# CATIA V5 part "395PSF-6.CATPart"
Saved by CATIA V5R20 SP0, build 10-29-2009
Part number: 395PSF-6
Source: Unknown
Property "ARTICLENO": "395PSF-6"
Property "BOMINFO": "395PSF-6"
Property "CODE": "395PSF-6"
Property "D": "78.000"
Property "D1": "95.000"
Property "H": "11.000"
Property "L": "421.500"
Property "L1": "14.000"
Property "L2": "355.000"
Property "L3": "25.000"
Property "L4": "14.000"
Property "LINA": "395PSF-6"
Property "MAXLOAD": "30000 Kg"
Property "MDW": "60000 Kg"
Property "NB": "395PSF-6"
Property "NBSYN": "$CODE."
Property "NN": "395PSF"
Property "NT": "FIAT Lifting Pins"
Property "SUPPLIER": "CF"
Bounding box of the stored display mesh (mm): x 0 to 421.5, y -50 to 47.5, z -47.5 to 47.5
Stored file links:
  C:\Users\Utente\Desktop\3D files 395PSF\395PSF-6.CATPart
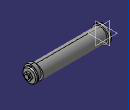
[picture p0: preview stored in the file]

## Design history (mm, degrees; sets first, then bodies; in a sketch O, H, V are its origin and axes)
Body1 "Geometry.1" (main body)
  Solid1 "395PSF-6.catpart": solid without history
